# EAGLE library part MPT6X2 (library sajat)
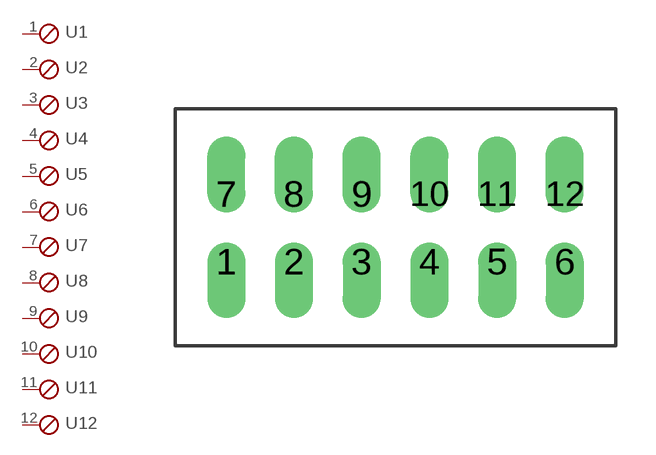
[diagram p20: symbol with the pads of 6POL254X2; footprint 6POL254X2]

Designator prefix -; gates 1=SKB 2=SKB 3=SKB 4=SKB 5=SKB 6=SKB 7=SKB 8=SKB 9=SKB 10=SKB 11=SKB 12=SKB

## MPT6X2  [6POL254X2]
1  1:1  pas
2  2:1  pas
3  3:1  pas
4  4:1  pas
5  5:1  pas
6  6:1  pas
7  7:1  pas
8  8:1  pas
9  9:1  pas
10  10:1  pas
11  11:1  pas
12  12:1  pas

## Footprint 6POL254X2 (pad centres in mm)
drill 0.3 pad 1.422 offset: 1 -6.35,-1.27; 2 -3.81,-1.27; 3 -1.27,-1.27; 4 1.27,-1.27; 5 3.81,-1.27; 6 6.35,-1.27; 7 -6.35,1.27; 8 -3.81,1.27; 9 -1.27,1.27; 10 1.27,1.27; 11 3.81,1.27; 12 6.35,1.27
